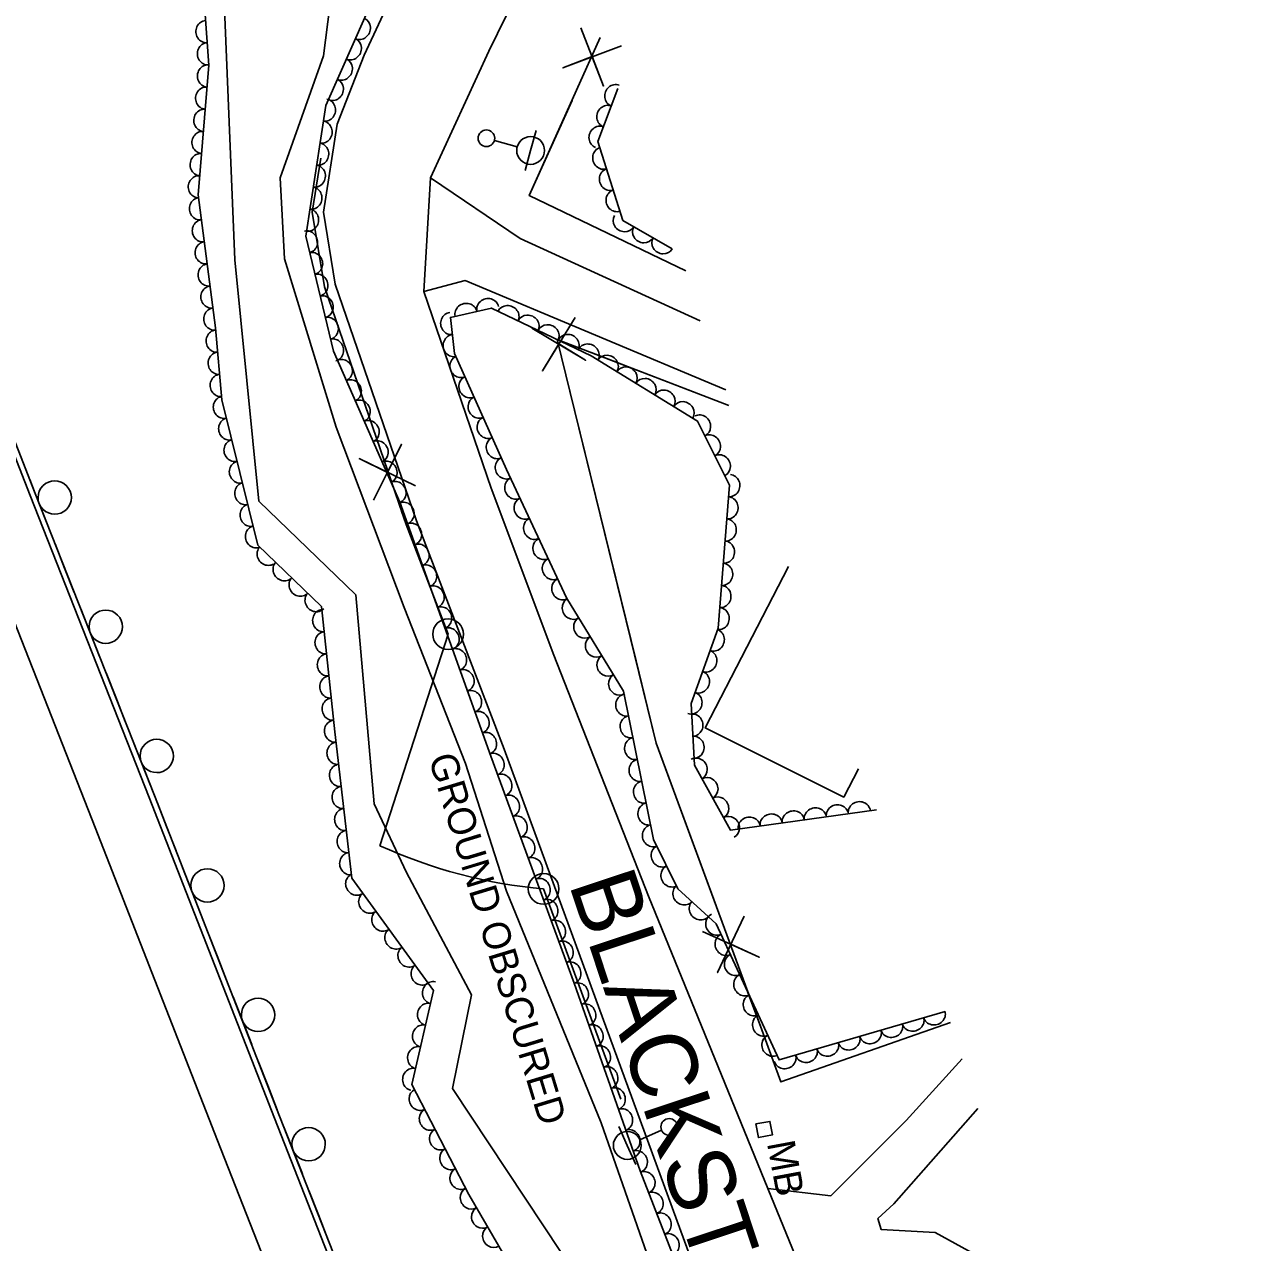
# Model space of a CAD drawing. Extents: x 1746719 to 1766531, y 631721 to 662391.
# Drawn here: x 1754679.2 to 1754897.3, y 649101 to 649320.2 of the extents above; entities that cross this region are included whole.
import ezdxf

# ---------------------------------------------------------------- set-up
doc = ezdxf.new("R2010")
doc.units = 0
for name, color, linetype in [('SURVEY - AERIAL SURVEY - Photo Control - Points - Elevations', 7, 'Continuous'), ('SURVEY - AERIAL SURVEY - Photo Control - Points - Locators', 7, 'Continuous'), ('SURVEY - AERIAL SURVEY - Photo Control - Points - Numbers', 7, 'Continuous'), ('SURVEY - AERIAL SURVEY - Photo Control with Text', 7, 'Continuous'), ('SURVEY - CENTERLINE - Existing Roads - Development', 7, 'Continuous'), ('SURVEY - CENTERLINE - Existing Roads Curve Text', 7, 'Continuous'), ('SURVEY - CONTROL - Points - Numbers', 7, 'Continuous')]:
    doc.layers.add(name, color=color, linetype=linetype)

msp = doc.modelspace()

# ---------------------------------------------------------------- linework, layer by layer
at = {"layer": 'SURVEY - AERIAL SURVEY - Photo Control - Points - Elevations'}
for points in [[(1755115.35, 648210.44), (1755101.05, 648241.68), (1755075.7, 648298.73), (1755049.35, 648357.31), (1755030.85, 648399.58), (1755014.73, 648435.52), (1754992.75, 648485.36), (1754969, 648539.7), (1754947.21, 648588.87), (1754915.3, 648661.1), (1754893.71, 648710.14), (1754872.45, 648759.46), (1754844.58, 648825.55), (1754823.17, 648877.77), (1754798.13, 648938.26), (1754769.55, 649009.24), (1754747.62, 649063.55), (1754724.17, 649123.36), (1754701.64, 649181.06), (1754680.19, 649235.39), (1754656.46, 649296.06), (1754637.62, 649345.88), (1754614.74, 649407.39), (1754586.53, 649484.29)], [(1755104.99, 648205.74), (1755065.66, 648294.24), (1755039.29, 648352.85), (1755020.79, 648395.13), (1755004.68, 648431.05), (1754982.68, 648480.94), (1754958.93, 648535.27), (1754937.15, 648584.41), (1754905.24, 648656.66), (1754883.62, 648705.74), (1754862.33, 648755.14), (1754834.42, 648821.33), (1754813, 648873.58), (1754787.94, 648934.1), (1754759.35, 649005.13), (1754737.4, 649059.49), (1754713.93, 649119.35), (1754691.4, 649177.04), (1754669.95, 649231.36), (1754646.2, 649292.11), (1754627.32, 649342.01), (1754604.42, 649403.58), (1754576.2, 649480.5)], [(1754799.25, 649097.63), (1754788.64, 649126.6), (1754765.49, 649189.75), (1754749.71, 649230.84), (1754735.11, 649273.43), (1754732.97, 649286.36), (1754735.47, 649302.21), (1754740.32, 649314.62), (1754751.02, 649337.63), (1754763.61, 649364.74), (1754765, 649367.32)], [(1754775.18, 649340.83), (1754762.72, 649315.33), (1754752.26, 649292.57), (1754751.01, 649272.12), (1754763.14, 649236.71), (1754774.44, 649206.67), (1754791.48, 649163.32), (1754812.91, 649110.69), (1754825.04, 649081.06)], [(1754752.26, 649292.57), (1754768.34, 649281.64), (1754800.76, 649266.84)], [(1754751.01, 649272.12), (1754758.47, 649274.07), (1754805.37, 649254.41)], [(1754812.91, 649110.69), (1754824.28, 649109.4), (1754837.78, 649122.95), (1754847.89, 649134.03)], [(1754850.71, 649125.06), (1754835.58, 649107.96), (1754832.74, 649105.28), (1754833.31, 649103.34), (1754843.03, 649102.75), (1754862.85, 649091.83)]]:
    msp.add_lwpolyline(points, dxfattribs=at)
at = {"layer": 'SURVEY - AERIAL SURVEY - Photo Control - Points - Locators'}
for points in [[(1754705.5, 649466.8), (1754707.71, 649431.71), (1754703.38, 649408.64), (1754703.04, 649391.97), (1754719.7, 649376.33), (1754731.86, 649372.82), (1754733.24, 649351.32), (1754735.68, 649335.71), (1754732.99, 649314.51), (1754725.17, 649292.57), (1754725.95, 649277.97), (1754735.26, 649247.7), (1754747.52, 649215.21), (1754758.56, 649187.19), (1754765.88, 649164.17), (1754782.97, 649122.5), (1754801.95, 649068.09)], [(1754779.06, 649094.19), (1754756.2, 649128.67), (1754759.6, 649145.52), (1754747.92, 649167.58), (1754742.11, 649179.92), (1754738.82, 649217.5), (1754721.36, 649234.37), (1754717.05, 649277.77), (1754715.23, 649321.53), (1754712.87, 649347.7), (1754701.09, 649373.39), (1754682.93, 649401.74), (1754668.94, 649428.44)]]:
    msp.add_lwpolyline(points, dxfattribs=at)
at = {"layer": 'SURVEY - AERIAL SURVEY - Photo Control - Points - Numbers'}
for points in [[(1754825.74, 648874.19), (1754799.05, 648938.64), (1754770.48, 649009.61), (1754748.55, 649063.92), (1754725.1, 649123.72), (1754702.57, 649181.43), (1754681.12, 649235.75), (1754657.4, 649296.42), (1754638.55, 649346.23), (1754615.68, 649407.74), (1754587.47, 649484.64)], [(1754683.52, 649229.68), (1754681.12, 649235.75), (1754680.15, 649238.24)], [(1754686.42, 649222.34), (1754684.69, 649226.71)], [(1754688.14, 649217.96), (1754686.42, 649222.34)], [(1754692.7, 649206.43), (1754689.32, 649214.99)], [(1754695.6, 649199.08), (1754693.87, 649203.45)], [(1754697.32, 649194.71), (1754695.6, 649199.08)], [(1754701.88, 649183.18), (1754698.5, 649191.73)], [(1754704.76, 649175.82), (1754703.05, 649180.2)], [(1754706.47, 649171.44), (1754704.76, 649175.82)], [(1754710.98, 649159.89), (1754707.63, 649168.46)], [(1754713.85, 649152.53), (1754712.14, 649156.91)], [(1754715.56, 649148.16), (1754713.85, 649152.53)], [(1754720.07, 649136.6), (1754716.72, 649145.18)], [(1754722.95, 649129.25), (1754721.24, 649133.62)], [(1754724.66, 649124.87), (1754722.95, 649129.25)], [(1754729.18, 649113.32), (1754725.82, 649121.89)], [(1754732.06, 649105.97), (1754730.35, 649110.34)], [(1754733.78, 649101.59), (1754732.06, 649105.97)]]:
    msp.add_lwpolyline(points, dxfattribs=at)
for centre, start, end in [((1754684.63, 649235.02), 314.8106, 314.7966), ((1754693.81, 649211.77), 314.8106, 314.7966), ((1754702.99, 649188.52), 314.8106, 314.7966), ((1754712.11, 649165.23), 314.601, 314.587), ((1754721.21, 649141.94), 314.601, 314.587), ((1754730.31, 649118.66), 314.6823, 314.6683)]:
    msp.add_arc(centre, 3, start, end, dxfattribs=at)
at = {"layer": 'SURVEY - AERIAL SURVEY - Photo Control with Text'}
for points in [[(1754703.32, 649477.85), (1754714.3, 649459.18), (1754713.58, 649429.71), (1754705.29, 649399.33), (1754715.28, 649388.68), (1754731.61, 649381.7), (1754745.15, 649376.9), (1754748.79, 649373.22), (1754748.18, 649366.03), (1754739.74, 649362.98), (1754741.87, 649347.44), (1754747.89, 649338.35), (1754733.4, 649305.55), (1754729.78, 649282.05), (1754734.78, 649261.34), (1754746.71, 649234.19), (1754763.07, 649188.48), (1754778.09, 649147.64), (1754789.94, 649113.86), (1754802.78, 649080.8)], [(1754772.76, 649086.19), (1754759.11, 649109.63), (1754748.9, 649129.41), (1754752.76, 649146.35), (1754738.08, 649166.53), (1754735.05, 649192.85), (1754732.65, 649215.41), (1754721.19, 649226.48), (1754714.7, 649252.6), (1754713.53, 649265.58), (1754710.42, 649289.47), (1754712.34, 649312.8), (1754710.57, 649337.8), (1754699.89, 649367.33), (1754680.76, 649396.69), (1754667.56, 649416.66)], [(1754795.74, 649279.77), (1754786.83, 649284.88), (1754782.35, 649299.11), (1754785.95, 649308.61)], [(1754844.8, 649142.57), (1754814.96, 649133.82), (1754803.6, 649158.33), (1754796.71, 649164.64), (1754792.38, 649173.51), (1754786.93, 649200.19), (1754776.69, 649216.95), (1754765.93, 649240.04), (1754756.58, 649260.94), (1754755.82, 649267.44), (1754763.2, 649269.1), (1754781.12, 649260.5), (1754800.3, 649248.77), (1754806.03, 649237.27), (1754803.96, 649211.51), (1754799.15, 649197.95), (1754799.74, 649186.88), (1754806.2, 649175.17), (1754832.48, 649178.85)]]:
    msp.add_lwpolyline(points, dxfattribs=at)
for centre, major_axis in [((1754711.91, 649318.85), (-0.14, 2)), ((1754739.53, 649319.41), (-0.81, -1.83)), ((1754737.91, 649315.76), (-0.81, -1.83)), ((1754712.19, 649314.86), (-0.14, 2)), ((1754736.29, 649312.1), (-0.81, -1.83)), ((1754712.18, 649310.88), (0.16, 1.99)), ((1754711.85, 649306.89), (0.16, 1.99)), ((1754734.68, 649308.44), (-0.81, -1.83)), ((1754785.47, 649307.35), (0.71, 1.87)), ((1754733.27, 649304.72), (-0.31, -1.98)), ((1754711.53, 649302.9), (0.16, 1.99)), ((1754784.06, 649303.61), (0.71, 1.87)), ((1754732.66, 649300.76), (-0.31, -1.98)), ((1754782.64, 649299.87), (0.71, 1.87)), ((1754711.2, 649298.92), (0.16, 1.99)), ((1754732.05, 649296.81), (-0.31, -1.98)), ((1754783.31, 649296.07), (-0.6, 1.91)), ((1754710.87, 649294.93), (0.16, 1.99)), ((1754731.44, 649292.86), (-0.31, -1.98)), ((1754784.51, 649292.25), (-0.6, 1.91)), ((1754710.54, 649290.94), (0.16, 1.99)), ((1754710.75, 649286.97), (-0.26, 1.98)), ((1754730.83, 649288.9), (-0.31, -1.98)), ((1754785.71, 649288.44), (-0.6, 1.91)), ((1754730.22, 649284.95), (-0.31, -1.98)), ((1754711.26, 649283), (-0.26, 1.98)), ((1754787.07, 649284.75), (-1.73, 1)), ((1754730.03, 649281.02), (0.47, -1.94)), ((1754790.54, 649282.76), (-1.73, 1)), ((1754711.78, 649279.04), (-0.26, 1.98)), ((1754794.01, 649280.77), (-1.73, 1)), ((1754730.96, 649277.13), (0.47, -1.94)), ((1754712.3, 649275.07), (-0.26, 1.98)), ((1754731.9, 649273.24), (0.47, -1.94)), ((1754712.81, 649271.1), (-0.26, 1.98)), ((1754732.84, 649269.35), (0.47, -1.94)), ((1754758.63, 649268.08), (1.95, 0.44)), ((1754762.54, 649268.95), (1.95, 0.44)), ((1754766.19, 649267.67), (1.8, -0.87)), ((1754713.33, 649267.14), (-0.26, 1.98)), ((1754733.78, 649265.46), (0.47, -1.94)), ((1754755.95, 649266.33), (-0.23, 1.99)), ((1754769.8, 649265.94), (1.8, -0.87)), ((1754713.75, 649263.16), (-0.18, 1.99)), ((1754773.4, 649264.21), (1.8, -0.87)), ((1754734.72, 649261.57), (0.47, -1.94)), ((1754756.41, 649262.36), (-0.23, 1.99)), ((1754777.01, 649262.48), (1.8, -0.87)), ((1754780.62, 649260.75), (1.8, -0.87)), ((1754714.11, 649259.18), (-0.18, 1.99)), ((1754784.06, 649258.71), (1.71, -1.04)), ((1754736.29, 649257.9), (0.8, -1.83)), ((1754757.63, 649258.59), (-0.82, 1.83)), ((1754787.47, 649256.62), (1.71, -1.04)), ((1754714.47, 649255.19), (-0.18, 1.99)), ((1754737.9, 649254.24), (0.8, -1.83)), ((1754759.26, 649254.94), (-0.82, 1.83)), ((1754790.88, 649254.53), (1.71, -1.04)), ((1754794.29, 649252.44), (1.71, -1.04)), ((1754715.04, 649251.24), (-0.48, 1.94)), ((1754739.51, 649250.57), (0.8, -1.83)), ((1754760.9, 649251.29), (-0.82, 1.83)), ((1754797.7, 649250.36), (1.71, -1.04)), ((1754800.73, 649247.91), (0.89, -1.79)), ((1754716, 649247.36), (-0.48, 1.94)), ((1754741.12, 649246.91), (0.8, -1.83)), ((1754762.53, 649247.64), (-0.82, 1.83)), ((1754716.97, 649243.48), (-0.48, 1.94)), ((1754742.73, 649243.25), (0.8, -1.83)), ((1754764.16, 649243.99), (-0.82, 1.83)), ((1754802.51, 649244.33), (0.89, -1.79)), ((1754804.29, 649240.75), (0.89, -1.79)), ((1754717.93, 649239.6), (-0.48, 1.94)), ((1754744.34, 649239.59), (0.8, -1.83)), ((1754765.8, 649240.34), (-0.82, 1.83)), ((1754806.02, 649237.16), (-0.16, -1.99)), ((1754718.9, 649235.72), (-0.48, 1.94)), ((1754745.94, 649235.93), (0.8, -1.83)), ((1754767.48, 649236.71), (-0.84, 1.81)), ((1754747.42, 649232.21), (0.67, -1.88)), ((1754769.17, 649233.09), (-0.84, 1.81)), ((1754805.7, 649233.17), (-0.16, -1.99)), ((1754719.86, 649231.83), (-0.48, 1.94)), ((1754720.82, 649227.95), (-0.48, 1.94)), ((1754748.76, 649228.44), (0.67, -1.88)), ((1754770.86, 649229.46), (-0.84, 1.81)), ((1754805.38, 649229.19), (-0.16, -1.99)), ((1754772.55, 649225.83), (-0.84, 1.81)), ((1754722.98, 649224.75), (-1.44, 1.39)), ((1754750.11, 649224.68), (0.67, -1.88)), ((1754805.06, 649225.2), (-0.16, -1.99)), ((1754725.85, 649221.97), (-1.44, 1.39)), ((1754774.24, 649222.21), (-0.84, 1.81)), ((1754804.74, 649221.21), (-0.16, -1.99)), ((1754751.46, 649220.91), (0.67, -1.88)), ((1754728.73, 649219.19), (-1.44, 1.39)), ((1754752.81, 649217.15), (0.67, -1.88)), ((1754775.93, 649218.58), (-0.84, 1.81)), ((1754804.42, 649217.22), (-0.16, -1.99)), ((1754731.6, 649216.41), (-1.44, 1.39)), ((1754777.84, 649215.07), (-1.04, 1.71)), ((1754732.92, 649212.87), (-0.21, 1.99)), ((1754754.16, 649213.38), (0.67, -1.88)), ((1754804.1, 649213.24), (-0.16, -1.99)), ((1754779.92, 649211.66), (-1.04, 1.71)), ((1754733.34, 649208.89), (-0.21, 1.99)), ((1754755.5, 649209.61), (0.67, -1.88)), ((1754803.2, 649209.37), (-0.67, -1.89)), ((1754756.85, 649205.85), (0.67, -1.88)), ((1754782.01, 649208.25), (-1.04, 1.71)), ((1754733.76, 649204.91), (-0.21, 1.99)), ((1754784.09, 649204.83), (-1.04, 1.71)), ((1754801.87, 649205.6), (-0.67, -1.89)), ((1754758.2, 649202.08), (0.67, -1.88)), ((1754800.53, 649201.83), (-0.67, -1.89)), ((1754734.19, 649200.94), (-0.21, 1.99)), ((1754786.18, 649201.42), (-1.04, 1.71)), ((1754759.55, 649198.32), (0.67, -1.88)), ((1754787.44, 649197.68), (-0.4, 1.96)), ((1754799.19, 649198.06), (-0.67, -1.89)), ((1754734.61, 649196.96), (-0.21, 1.99)), ((1754735.04, 649192.98), (-0.21, 1.99)), ((1754760.9, 649194.55), (0.67, -1.88)), ((1754788.24, 649193.76), (-0.4, 1.96)), ((1754799.36, 649194.07), (0.11, -2)), ((1754762.24, 649190.78), (0.67, -1.88)), ((1754735.49, 649189.01), (-0.23, 1.99)), ((1754789.04, 649189.85), (-0.4, 1.96)), ((1754799.57, 649190.08), (0.11, -2)), ((1754763.6, 649187.02), (0.69, -1.88)), ((1754800.12, 649186.18), (0.97, -1.75)), ((1754735.95, 649185.03), (-0.23, 1.99)), ((1754789.84, 649185.93), (-0.4, 1.96)), ((1754764.99, 649183.27), (0.69, -1.88)), ((1754790.64, 649182.01), (-0.4, 1.96)), ((1754802.05, 649182.68), (0.97, -1.75)), ((1754736.41, 649181.06), (-0.23, 1.99)), ((1754766.37, 649179.51), (0.69, -1.88)), ((1754791.44, 649178.09), (-0.4, 1.96)), ((1754803.98, 649179.18), (0.97, -1.75)), ((1754825.43, 649177.86), (1.98, 0.28)), ((1754829.39, 649178.42), (1.98, 0.28)), ((1754736.87, 649177.09), (-0.23, 1.99)), ((1754767.75, 649175.76), (0.69, -1.88)), ((1754805.92, 649175.68), (0.97, -1.75)), ((1754809.58, 649175.64), (1.98, 0.28)), ((1754813.54, 649176.2), (1.98, 0.28)), ((1754817.5, 649176.75), (1.98, 0.28)), ((1754821.47, 649177.31), (1.98, 0.28)), ((1754737.32, 649173.11), (-0.23, 1.99)), ((1754792.24, 649174.17), (-0.4, 1.96)), ((1754769.13, 649172.01), (0.69, -1.88)), ((1754737.78, 649169.14), (-0.23, 1.99)), ((1754793.84, 649170.52), (-0.88, 1.8)), ((1754770.51, 649168.25), (0.69, -1.88)), ((1754795.59, 649166.92), (-0.88, 1.8)), ((1754738.89, 649165.42), (-1.18, 1.62)), ((1754771.89, 649164.5), (0.69, -1.88)), ((1754797.78, 649163.66), (-1.48, 1.35)), ((1754741.24, 649162.18), (-1.18, 1.62)), ((1754773.27, 649160.74), (0.69, -1.88)), ((1754800.73, 649160.96), (-1.48, 1.35)), ((1754743.6, 649158.95), (-1.18, 1.62)), ((1754803.65, 649158.23), (-0.84, 1.81)), ((1754774.65, 649156.99), (0.69, -1.88)), ((1754745.95, 649155.72), (-1.18, 1.62)), ((1754776.03, 649153.24), (0.69, -1.88)), ((1754805.33, 649154.6), (-0.84, 1.81)), ((1754748.3, 649152.48), (-1.18, 1.62)), ((1754750.66, 649149.25), (-1.18, 1.62)), ((1754777.41, 649149.48), (0.69, -1.88)), ((1754807.01, 649150.97), (-0.84, 1.81)), ((1754808.69, 649147.34), (-0.84, 1.81)), ((1754752.67, 649145.94), (0.44, 1.95)), ((1754778.77, 649145.72), (0.66, -1.89)), ((1754810.38, 649143.71), (-0.84, 1.81)), ((1754751.78, 649142.04), (0.44, 1.95)), ((1754780.09, 649141.94), (0.66, -1.89)), ((1754842.88, 649142.01), (-1.92, -0.56)), ((1754750.89, 649138.14), (0.44, 1.95)), ((1754781.41, 649138.17), (0.66, -1.89)), ((1754812.06, 649140.08), (-0.84, 1.81)), ((1754835.2, 649139.76), (-1.92, -0.56)), ((1754839.04, 649140.88), (-1.92, -0.56)), ((1754813.74, 649136.45), (-0.84, 1.81)), ((1754827.52, 649137.5), (-1.92, -0.56)), ((1754831.36, 649138.63), (-1.92, -0.56)), ((1754750, 649134.24), (0.44, 1.95)), ((1754782.74, 649134.39), (0.66, -1.89)), ((1754819.85, 649135.25), (-1.92, -0.56)), ((1754823.69, 649136.38), (-1.92, -0.56)), ((1754816.01, 649134.13), (-1.92, -0.56)), ((1754749.11, 649130.34), (0.44, 1.95)), ((1754784.06, 649130.62), (0.66, -1.89)), ((1754785.39, 649126.84), (0.66, -1.89)), ((1754750.3, 649126.71), (-0.92, 1.78)), ((1754752.13, 649123.15), (-0.92, 1.78)), ((1754786.71, 649123.07), (0.66, -1.89)), ((1754753.97, 649119.6), (-0.92, 1.78)), ((1754788.03, 649119.3), (0.66, -1.89)), ((1754755.8, 649116.04), (-0.92, 1.78)), ((1754789.36, 649115.52), (0.66, -1.89)), ((1754757.64, 649112.49), (-0.92, 1.78)), ((1754790.75, 649111.77), (0.72, -1.86)), ((1754759.51, 649108.96), (-1.01, 1.73)), ((1754792.2, 649108.04), (0.72, -1.86)), ((1754761.52, 649105.5), (-1.01, 1.73)), ((1754793.65, 649104.31), (0.72, -1.86)), ((1754763.53, 649102.04), (-1.01, 1.73)), ((1754795.1, 649100.59), (0.72, -1.86))]:
    msp.add_ellipse(centre, major_axis=major_axis, ratio=0.940188, start_param=0, end_param=3.141593, dxfattribs=at)
at = {"layer": 'SURVEY - CENTERLINE - Existing Roads - Development'}
for p, q in [((1754770.24, 649297.47), (1754771.24, 649301.09)), ((1754763.73, 649299.27), (1754767.83, 649298.14)), ((1754770.24, 649297.47), (1754769.24, 649293.86)), ((1754787.63, 649118.44), (1754786.12, 649121.87)), ((1754793.81, 649121.17), (1754789.92, 649119.45)), ((1754787.63, 649118.44), (1754789.15, 649115.01))]:
    msp.add_line(p, q, dxfattribs=at)
for centre, radius in [((1754762.29, 649299.67), 1.5), ((1754770.24, 649297.47), 2.5), ((1754795.18, 649121.77), 1.5), ((1754787.63, 649118.44), 2.5)]:
    msp.add_circle(centre, radius, dxfattribs=at)
at = {"layer": 'SURVEY - CENTERLINE - Existing Roads Curve Text'}
for p, q in [((1754755.41, 649210.44), (1754743.11, 649172.38)), ((1754812.29, 649121.32), (1754812.29, 649121.32))]:
    msp.add_line(p, q, dxfattribs=at)
for points in [[(1754798.2, 649275.84), (1754770.01, 649289.36), (1754782.79, 649317.8)], [(1754779.3, 649319.55), (1754783.36, 649309.06), (1754781.35, 649314.35), (1754776.07, 649312.34), (1754786.6, 649316.27)], [(1754798.2, 649275.84), (1754770.01, 649289.36), (1754777.7, 649306.46)], [(1754732.48, 649296.07), (1754730.95, 649286.35), (1754733.17, 649272.94), (1754741.78, 649247.8)], [(1754732.48, 649296.07), (1754730.95, 649286.35), (1754733.17, 649272.94), (1754747.83, 649230.16), (1754755.4, 649210.44)], [(1754770.48, 649265.48), (1754780.14, 649259.72), (1754775.3, 649262.65), (1754772.37, 649257.81), (1754778.25, 649267.39)], [(1754845.79, 649140.54), (1754815.29, 649129.87), (1754811.58, 649139.88), (1754792.85, 649190.83), (1754775, 649263.44), (1754805.88, 649251.6)], [(1754781.12, 649261.1), (1754805.88, 649251.6)], [(1754789.21, 649205.62), (1754777.28, 649254.18)], [(1754749.56, 649237.15), (1754739.43, 649242.03), (1754744.51, 649239.54), (1754747, 649244.62), (1754741.99, 649234.55)], [(1754747, 649232.57), (1754747.83, 649230.16), (1754755.4, 649210.44)], [(1754816.63, 649222.6), (1754801.67, 649193.57), (1754826.58, 649181.13), (1754829.24, 649186.22)], [(1754803.6, 649161.57), (1754792.85, 649190.83), (1754789.21, 649205.62)], [(1754772.59, 649164.59), (1754786.45, 649126.78)], [(1754772.59, 649164.59), (1754786.45, 649126.78)], [(1754801.15, 649156.94), (1754811.38, 649152.29), (1754806.25, 649154.66), (1754803.87, 649149.53), (1754808.66, 649159.7)], [(1754845.79, 649140.54), (1754815.29, 649129.87), (1754811.58, 649139.88), (1754809.16, 649146.46)]]:
    msp.add_lwpolyline(points, dxfattribs=at)
msp.add_lwpolyline([(1754810.78, 649122.31), (1754813.29, 649122.77), (1754813.75, 649120.32), (1754811.24, 649119.85)], close=True, dxfattribs=at)
for centre in [(1754755.4, 649210.44), (1754772.59, 649164.59)]:
    msp.add_circle(centre, 2.76, dxfattribs=at)
msp.add_arc((1754780.88, 649255.61), 91.4, 245.5971, 264.796, dxfattribs=at)

# ---------------------------------------------------------------- texts
at = {"layer": 'SURVEY - AERIAL SURVEY - Photo Control - Points - Locators'}
msp.add_text('GROUND OBSCURED', height=5, rotation=286.9107, dxfattribs=at).set_placement((1754751.84, 649188.16))
at = {"layer": 'SURVEY - CENTERLINE - Existing Roads Curve Text'}
msp.add_text('MB', height=5, rotation=280.5858, dxfattribs=at).set_placement((1754812.75, 649118.86))
at = {"layer": 'SURVEY - CONTROL - Points - Numbers'}
msp.add_text('BLACKSTONE PL.', height=12, rotation=288.3525, dxfattribs=at).set_placement((1754777.07, 649165.56))

doc.saveas('drawing.dxf')
